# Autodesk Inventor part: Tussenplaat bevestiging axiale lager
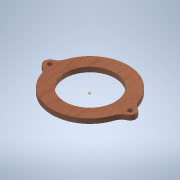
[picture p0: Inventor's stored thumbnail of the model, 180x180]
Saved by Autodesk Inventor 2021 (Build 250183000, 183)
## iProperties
Manager: Pierloot J.
Company: Emmaüs Bovenbouw Aalter
Created: 2015-08
Part Number: Tussenplaat bevestiging axiale lager
Material: S235
Catalog Web Link: http://emmausbovenbouw.op-weg.be/
Vendor: Emmaüsinstituut Bovenbouw Aalter
Document SubType Name: Modeling
Designer: Pierlootj
Engineer: Pierloot J.
Manufacturer: Standard
Standards Organization: Custom
Density: 7.86 g/cm^3
Appearance: Steel
Title: Algemene titel
Subject: Specifieke titel
Author: Pierlootj
Keywords: Ruwe Ø xxxxx
Comments: Opmerking
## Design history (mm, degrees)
sketch "Sketch1"
  geometry: L1 (0, 2.858)-(0, -2.858); L2 (-5.777, 0)-(5.777, 0); L3 (-40, 0)-(-35, 0); L4 (40, 0)-(35, 0); C1 r 26.3 at (0, 0); C2 r 2.5 at (-35, 0); C3 r 2.5 at (35, 0); A1 r 40 centre (0, 0) between (-40, 0) and (40, 0); 2 further points
  constraints: 8 end point, 5 coincident, 4 centre point, 3 horizontal, 2 midpoint, 2 point on circle, 1 vertical
  dimensions: "d0" = 52.6 diameter of C1; "d1" = 80 diameter of A1; "d4" = 5 distance of L3.start L3.end; "d5" = 5 diameter of C2; "d6" = 5 distance of L4.start L4.end; "d7" = 5 diameter of C3
extrude "Extrusion1" new body sketch "Sketch1" distance "d2" = 5; taper "d3" = 0 deg
sketch "Sketch4"
  geometry: L1 (0, 0)-(-42, 0); L2 (-42, 0)-(42, 0); C1 r 2.5 at (-42, 0); C2 r 6 at (-42, 0); C3 r 2.5 at (42, 0); C4 r 6 at (42, 0)
  constraints: 4 centre point, 4 coincident, 4 end point, 1 horizontal, 1 point on line
  dimensions: "d19" = 42 distance of L1.start L1.end; "d20" = 84 distance of L1.end L2.end; "d21" = 5 diameter of C1; "d22" = 12 diameter of C2; "d23" = 5 diameter of C3; "d24" = 12 diameter of C4
extrude "Extrusion5" join sketch "Sketch4" distance "d25" = 5; taper "d26" = 0 deg
fillet "Fillet2" dims "d27" = 12
extrude "Extrusion6" cut sketch "Sketch4" distance "d28" = 5; taper "d29" = 0 deg
body "Solid1"
